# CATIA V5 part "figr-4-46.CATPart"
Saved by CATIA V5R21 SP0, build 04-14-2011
Part number: Part1
Bounding box of the stored display mesh (mm): x -89.975 to 89.975, y -89.975 to 89.975, z 0 to 190
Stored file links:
  D:\CATIA V5R21 E-RESOURCES\CATIA-V5R21\catia-v5r21-prt\c04-catia-v5r20-prt\catia-v5r21-figr-4-46.CATPart
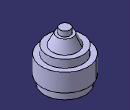
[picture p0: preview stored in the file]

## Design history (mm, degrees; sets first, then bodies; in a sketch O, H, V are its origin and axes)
Set1
  Line1 "Y Axis": stored without definition
  Line2 "Y Axis": stored without definition
  Line3 "X Axis": stored without definition
  Line4 "Z Axis": stored without definition
Body1 (main body)
  Sketch1 on yz-plane, origin (0, 0, 0), H (0, 1, 0), V (0, 0, 1)
    line L1 (0, 0) -> (80, 0)
    line L2 (80, 0) -> (80, 30)
    line L3 (80, 30) -> (90, 30)
    line L4 (90, 30) -> (90, 100)
    line L5 (90, 100) -> (70, 100)
    line L6 (70, 100) -> (70, 130)
    line L7 (70, 130) -> (50, 130)
    line L8 (50, 130) -> (30, 170)
    line L9 (30, 170) -> (20, 170)
    line L10 (20, 170) -> (20, 190)
    line L11 (20, 190) -> (0, 190)
    point P11 (0, 190)
    line L12 (0, 190) -> (0, 0)
    axis line L13 (0, -40) -> (0, 230)
    point P12 (0, -40)
    point P13 (0, 230)
    horizontal: L1 H, L3 H, L5 H, L7 H, L9 H, L11 H
    vertical: L2 V, L4 V, L6 V, L10 V, L12 V, L13 V
    coincidence: P11 V, P12 V, P13 L8
  Shaft1: profile Sketch1, axis Sketch1.L13, angle 360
